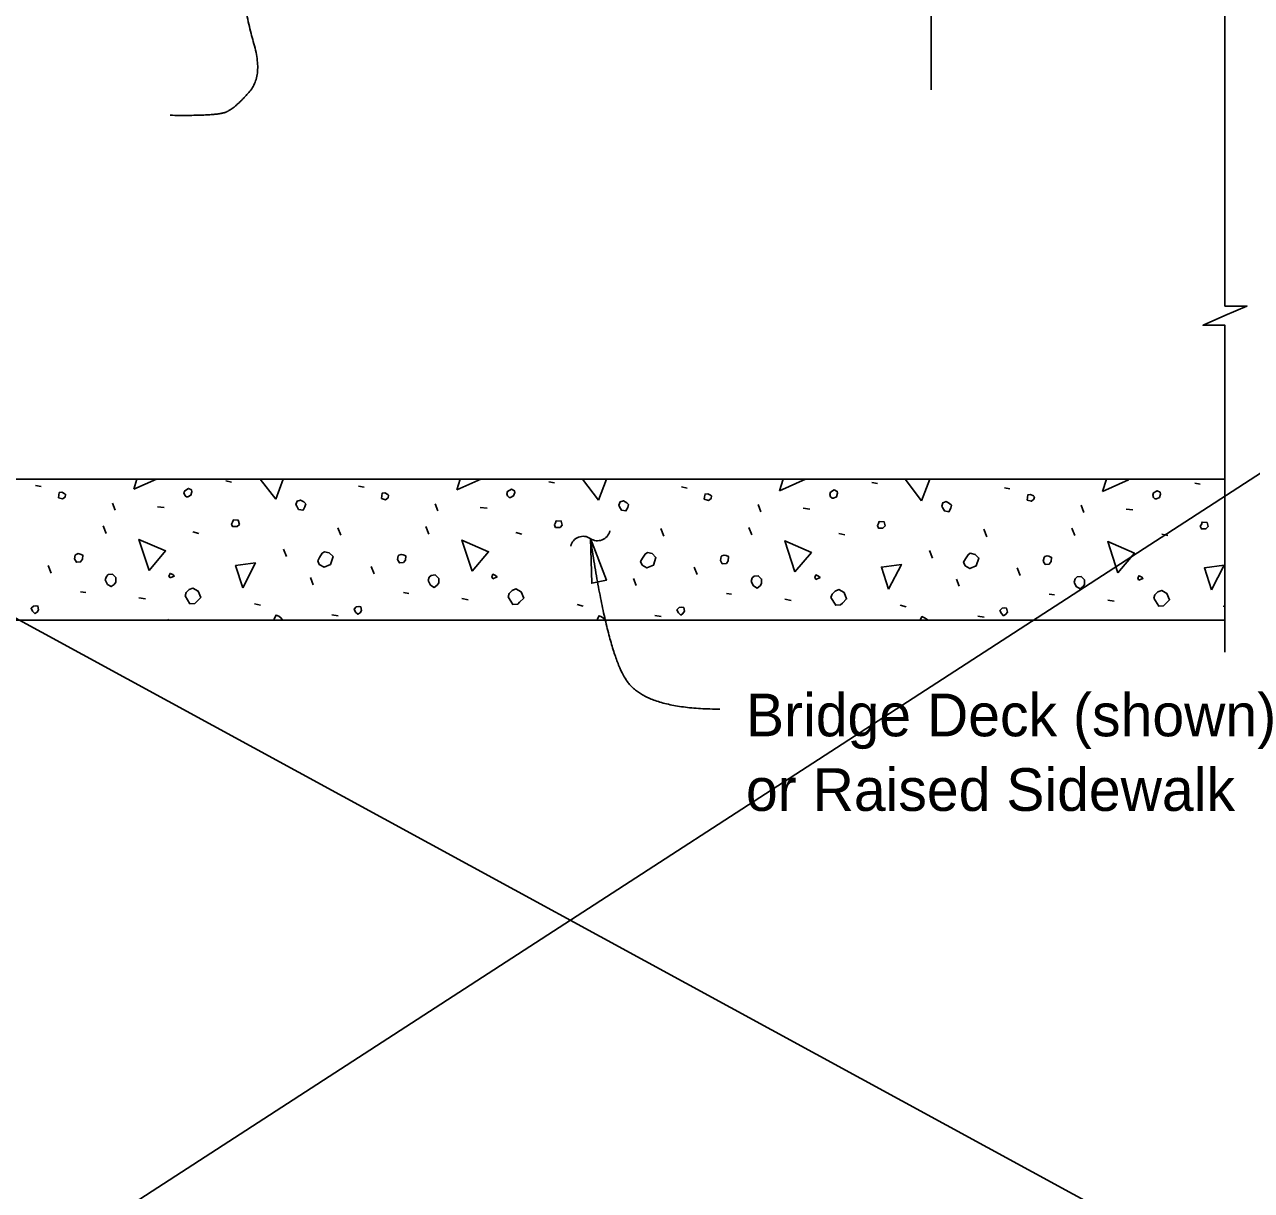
# Model space of a CAD drawing. Extents: x 110698 to 110915, y 110390 to 110472.
# Drawn here: x 110792.55 to 110798.34, y 110408.16 to 110413.66 of the extents above; entities that cross this region are included whole.
import ezdxf

# ---------------------------------------------------------------- set-up
doc = ezdxf.new("R2010")
doc.units = 0
for name, color, linetype in [('AdhocPoint_dp', 7, 'Continuous'), ('PlotBorder_dp', 7, 'Continuous'), ('SheetBorder_dp', 7, 'Continuous'), ('SheetLines_dp', 7, 'Continuous')]:
    doc.layers.add(name, color=color, linetype=linetype)

msp = doc.modelspace()

# ---------------------------------------------------------------- linework, layer by layer
at = {"layer": 'AdhocPoint_dp'}
msp.add_line((110796.8255, 110422.1361), (110796.8255, 110413.3542), dxfattribs=at)
at = {"layer": 'PlotBorder_dp'}
msp.add_lwpolyline([(110798.2126, 110413.7679), (110798.2126, 110412.334), (110798.3159, 110412.334), (110798.2126, 110412.289), (110798.1092, 110412.244), (110798.2126, 110412.244), (110798.2126, 110410.7015)], dxfattribs=at)
msp.add_lwpolyline([(110795.2186, 110411.2375), (110795.2247, 110411.0264), (110795.2939, 110411.0402)], close=True, dxfattribs=at)
for centre, start, end in [((110795.1839, 110411.188), 55.45253, 167.17975), ((110795.2516, 110411.2862), 235.45253, 347.17975)]:
    msp.add_arc(centre, 0.0596, start, end, dxfattribs=at)
for points in [[(110793.2353, 110413.2345), (110793.4581, 110413.2309), (110793.543, 110413.2699), (110793.6739, 110413.4186), (110793.589, 110413.716), (110793.5465, 110413.9813)], [(110795.8288, 110410.4321), (110795.4884, 110410.4321), (110795.2993, 110410.6877), (110795.2186, 110411.2376)]]:
    msp.add_open_spline(points, degree=2, dxfattribs=at)
at = {"layer": 'SheetBorder_dp'}
for p, q in [((110792.6001, 110411.4876), (110792.6266, 110411.4823)), ((110793.4981, 110411.5088), (110793.5246, 110411.5035)), ((110794.1239, 110411.4841), (110794.1504, 110411.4788)), ((110795.0219, 110411.5053), (110795.0485, 110411.5)), ((110795.6477, 110411.4805), (110795.6742, 110411.4752)), ((110796.5458, 110411.5018), (110796.5723, 110411.4965)), ((110797.1715, 110411.477), (110797.1981, 110411.4717)), ((110798.0696, 110411.4982), (110798.0961, 110411.4929)), ((110792.9749, 110411.3709), (110792.9625, 110411.4045)), ((110793.1746, 110411.3869), (110793.2064, 110411.3833)), ((110794.4987, 110411.3674), (110794.4863, 110411.401)), ((110794.6984, 110411.3833), (110794.7303, 110411.3798)), ((110796.0225, 110411.3639), (110796.0101, 110411.3975)), ((110796.2223, 110411.3798), (110796.2541, 110411.3762)), ((110797.5463, 110411.3603), (110797.5339, 110411.3939)), ((110797.7461, 110411.3762), (110797.7779, 110411.3727)), ((110792.9324, 110411.2613), (110792.9183, 110411.2967)), ((110794.4563, 110411.2578), (110794.4421, 110411.2932)), ((110795.9801, 110411.2543), (110795.9659, 110411.2896)), ((110793.3426, 110411.2684), (110793.3708, 110411.2613)), ((110794.0408, 110411.2525), (110794.0267, 110411.2879)), ((110794.8664, 110411.2649), (110794.8947, 110411.2578)), ((110795.5646, 110411.249), (110795.5505, 110411.2843)), ((110796.3902, 110411.2613), (110796.4185, 110411.2543)), ((110797.0885, 110411.2454), (110797.0743, 110411.2808)), ((110797.5039, 110411.2507), (110797.4897, 110411.2861)), ((110797.914, 110411.2578), (110797.9423, 110411.2507)), ((110793.7845, 110411.1517), (110793.7704, 110411.1871)), ((110796.8321, 110411.1447), (110796.818, 110411.18)), ((110792.6743, 110411.074), (110792.6602, 110411.1093)), ((110794.1982, 110411.0704), (110794.184, 110411.1058)), ((110795.722, 110411.0669), (110795.7078, 110411.1022)), ((110797.2458, 110411.0634), (110797.2316, 110411.0987)), ((110793.91, 110411.0192), (110793.8976, 110411.0527)), ((110795.4338, 110411.0156), (110795.4215, 110411.0492)), ((110796.9576, 110411.0121), (110796.9453, 110411.0457)), ((110792.8122, 110410.9856), (110792.837, 110410.982)), ((110793.088, 110410.9573), (110793.1181, 110410.952)), ((110794.336, 110410.982), (110794.3608, 110410.9785)), ((110794.6118, 110410.9537), (110794.6419, 110410.9484)), ((110795.8599, 110410.9785), (110795.8846, 110410.975)), ((110796.1356, 110410.9502), (110796.1657, 110410.9449)), ((110797.3837, 110410.975), (110797.4084, 110410.9714)), ((110797.6594, 110410.9467), (110797.6895, 110410.9414)), ((110793.6325, 110410.929), (110793.6608, 110410.9219)), ((110795.1563, 110410.9255), (110795.1846, 110410.9184)), ((110796.6801, 110410.9219), (110796.7084, 110410.9149)), ((110798.2039, 110410.9184), (110798.2125, 110410.9162)), ((110793.2261, 110410.8512), (110793.2241, 110410.8565)), ((110793.9984, 110410.8777), (110794.0285, 110410.8724)), ((110794.7486, 110410.8512), (110794.7479, 110410.853)), ((110795.5222, 110410.8742), (110795.5523, 110410.8689)), ((110797.046, 110410.8707), (110797.0761, 110410.8654))]:
    msp.add_line(p, q, dxfattribs=at)
for points in [[(110793.0633, 110411.4699), (110793.078, 110411.5179)], [(110793.17, 110411.5179), (110793.0633, 110411.4699)], [(110793.3107, 110411.4346), (110793.3178, 110411.4346), (110793.332, 110411.4417), (110793.3373, 110411.4576), (110793.3355, 110411.4664), (110793.3213, 110411.4735), (110793.3037, 110411.4629), (110793.3001, 110411.4523), (110793.3037, 110411.4417), (110793.3107, 110411.4346)], [(110793.7332, 110411.4222), (110793.6605, 110411.5179)], [(110793.769, 110411.5179), (110793.7332, 110411.4222)], [(110794.5871, 110411.4664), (110794.6029, 110411.5179)], [(110794.7017, 110411.5179), (110794.5871, 110411.4664)], [(110794.8346, 110411.431), (110794.8416, 110411.431), (110794.8558, 110411.4381), (110794.8611, 110411.454), (110794.8593, 110411.4629), (110794.8452, 110411.4699), (110794.8275, 110411.4593), (110794.8239, 110411.4487), (110794.8275, 110411.4381), (110794.8346, 110411.431)], [(110795.2571, 110411.4187), (110795.1816, 110411.5179)], [(110795.2941, 110411.5179), (110795.2571, 110411.4187)], [(110796.1109, 110411.4629), (110796.1278, 110411.5179)], [(110796.2323, 110411.5179), (110796.2329, 110411.5177), (110796.1109, 110411.4629)], [(110796.3584, 110411.4275), (110796.3654, 110411.4275), (110796.3796, 110411.4346), (110796.3849, 110411.4505), (110796.3831, 110411.4593), (110796.369, 110411.4664), (110796.3513, 110411.4558), (110796.3478, 110411.4452), (110796.3513, 110411.4346), (110796.3584, 110411.4275)], [(110796.7809, 110411.4151), (110796.7028, 110411.5179)], [(110796.8193, 110411.5179), (110796.7809, 110411.4151)], [(110797.6347, 110411.4593), (110797.6527, 110411.5179)], [(110797.7472, 110411.5179), (110797.7567, 110411.5141), (110797.6347, 110411.4593)], [(110792.7079, 110411.4293), (110792.7274, 110411.424), (110792.7398, 110411.4328), (110792.7415, 110411.4452), (110792.738, 110411.4487), (110792.7238, 110411.4558), (110792.7115, 110411.454), (110792.7097, 110411.4417), (110792.7079, 110411.4293)], [(110793.8322, 110411.3904), (110793.8411, 110411.3745), (110793.8623, 110411.3709), (110793.8711, 110411.3869), (110793.8747, 110411.401), (110793.8658, 110411.4098), (110793.8499, 110411.4187), (110793.834, 110411.4134), (110793.8287, 110411.3975), (110793.8322, 110411.3904)], [(110794.2317, 110411.4257), (110794.2512, 110411.4204), (110794.2636, 110411.4293), (110794.2653, 110411.4417), (110794.2618, 110411.4452), (110794.2477, 110411.4523), (110794.2353, 110411.4505), (110794.2335, 110411.4381), (110794.2317, 110411.4257)], [(110795.356, 110411.3869), (110795.3649, 110411.3709), (110795.3861, 110411.3674), (110795.3949, 110411.3833), (110795.3985, 110411.3975), (110795.3896, 110411.4063), (110795.3737, 110411.4151), (110795.3578, 110411.4098), (110795.3525, 110411.3939), (110795.356, 110411.3869)], [(110795.7556, 110411.4222), (110795.775, 110411.4169), (110795.7874, 110411.4257), (110795.7891, 110411.4381), (110795.7856, 110411.4417), (110795.7715, 110411.4487), (110795.7591, 110411.447), (110795.7573, 110411.4346), (110795.7556, 110411.4222)], [(110796.8799, 110411.3833), (110796.8887, 110411.3674), (110796.9099, 110411.3639), (110796.9188, 110411.3798), (110796.9223, 110411.3939), (110796.9134, 110411.4028), (110796.8975, 110411.4116), (110796.8816, 110411.4063), (110796.8763, 110411.3904), (110796.8799, 110411.3833)], [(110797.2794, 110411.4187), (110797.2988, 110411.4134), (110797.3112, 110411.4222), (110797.313, 110411.4346), (110797.3094, 110411.4381), (110797.2953, 110411.4452), (110797.2829, 110411.4434), (110797.2811, 110411.431), (110797.2794, 110411.4187)], [(110797.8822, 110411.424), (110797.8893, 110411.424), (110797.9034, 110411.431), (110797.9087, 110411.447), (110797.9069, 110411.4558), (110797.8928, 110411.4629), (110797.8751, 110411.4523), (110797.8716, 110411.4417), (110797.8751, 110411.431), (110797.8822, 110411.424)], [(110793.5299, 110411.2932), (110793.5512, 110411.2932), (110793.5618, 110411.3038), (110793.5565, 110411.3232), (110793.5335, 110411.325), (110793.5299, 110411.3144), (110793.5246, 110411.3055), (110793.5299, 110411.2932), (110793.5264, 110411.2967)], [(110795.0538, 110411.2896), (110795.075, 110411.2896), (110795.0856, 110411.3002), (110795.0803, 110411.3197), (110795.0573, 110411.3214), (110795.0538, 110411.3108), (110795.0485, 110411.302), (110795.0538, 110411.2896), (110795.0502, 110411.2932)], [(110796.5776, 110411.2861), (110796.5988, 110411.2861), (110796.6094, 110411.2967), (110796.6041, 110411.3161), (110796.5811, 110411.3179), (110796.5776, 110411.3073), (110796.5723, 110411.2985), (110796.5776, 110411.2861), (110796.574, 110411.2896)], [(110798.1014, 110411.2826), (110798.1226, 110411.2826), (110798.1332, 110411.2932), (110798.1279, 110411.3126), (110798.1049, 110411.3144), (110798.1014, 110411.3038), (110798.0961, 110411.2949), (110798.1014, 110411.2826), (110798.0979, 110411.2861)], [(110793.1357, 110411.0863), (110793.088, 110411.2331), (110793.2135, 110411.1783), (110793.1357, 110411.0863)], [(110793.9383, 110411.1146), (110793.9613, 110411.1022), (110793.9913, 110411.1146), (110794.0037, 110411.1517), (110793.986, 110411.1694), (110793.963, 110411.1747), (110793.9524, 110411.1676), (110793.9401, 110411.1482), (110793.9312, 110411.1323), (110793.9383, 110411.1146)], [(110794.6595, 110411.0828), (110794.6118, 110411.2295), (110794.7373, 110411.1747), (110794.6595, 110411.0828)], [(110796.1834, 110411.0793), (110796.1356, 110411.226), (110796.2611, 110411.1712), (110796.1834, 110411.0793)], [(110797.7072, 110411.0757), (110797.6594, 110411.2224), (110797.785, 110411.1676), (110797.7072, 110411.0757)], [(110792.7839, 110411.1411), (110792.7928, 110411.1252), (110792.8122, 110411.127), (110792.8211, 110411.1394), (110792.8228, 110411.1588), (110792.8105, 110411.1641), (110792.8016, 110411.1659), (110792.791, 110411.1623), (110792.7875, 110411.1588), (110792.7839, 110411.1411)], [(110793.5777, 110411.005), (110793.5441, 110411.1093), (110793.6378, 110411.1217), (110793.5777, 110411.005)], [(110794.3078, 110411.1376), (110794.3166, 110411.1217), (110794.336, 110411.1235), (110794.3449, 110411.1358), (110794.3467, 110411.1553), (110794.3343, 110411.1606), (110794.3254, 110411.1623), (110794.3148, 110411.1588), (110794.3113, 110411.1553), (110794.3078, 110411.1376)], [(110795.4621, 110411.1111), (110795.4851, 110411.0987), (110795.5151, 110411.1111), (110795.5275, 110411.1482), (110795.5098, 110411.1659), (110795.4869, 110411.1712), (110795.4763, 110411.1641), (110795.4639, 110411.1447), (110795.455, 110411.1288), (110795.4621, 110411.1111)], [(110795.8316, 110411.1341), (110795.8404, 110411.1182), (110795.8599, 110411.1199), (110795.8687, 110411.1323), (110795.8705, 110411.1517), (110795.8581, 110411.157), (110795.8493, 110411.1588), (110795.8386, 110411.1553), (110795.8351, 110411.1517), (110795.8316, 110411.1341)], [(110796.9859, 110411.1075), (110797.0089, 110411.0952), (110797.039, 110411.1075), (110797.0513, 110411.1447), (110797.0337, 110411.1623), (110797.0107, 110411.1676), (110797.0001, 110411.1606), (110796.9877, 110411.1411), (110796.9789, 110411.1252), (110796.9859, 110411.1075)], [(110797.3554, 110411.1305), (110797.3642, 110411.1146), (110797.3837, 110411.1164), (110797.3925, 110411.1288), (110797.3943, 110411.1482), (110797.3819, 110411.1535), (110797.3731, 110411.1553), (110797.3625, 110411.1517), (110797.3589, 110411.1482), (110797.3554, 110411.1305)], [(110792.9289, 110411.0421), (110792.9395, 110411.0209), (110792.9572, 110411.0103), (110792.9713, 110411.0209), (110792.9784, 110411.0315), (110792.9784, 110411.0527), (110792.9625, 110411.0687), (110792.943, 110411.0669), (110792.9342, 110411.058), (110792.9289, 110411.0421)], [(110793.2347, 110411.051), (110793.2542, 110411.0598), (110793.2471, 110411.0669), (110793.2347, 110411.0722), (110793.2294, 110411.0598), (110793.2347, 110411.051)], [(110794.4527, 110411.0386), (110794.4633, 110411.0174), (110794.481, 110411.0068), (110794.4951, 110411.0174), (110794.5022, 110411.028), (110794.5022, 110411.0492), (110794.4863, 110411.0651), (110794.4669, 110411.0634), (110794.458, 110411.0545), (110794.4527, 110411.0386)], [(110794.7585, 110411.0474), (110794.778, 110411.0563), (110794.7709, 110411.0634), (110794.7585, 110411.0687), (110794.7532, 110411.0563), (110794.7585, 110411.0474)], [(110795.9765, 110411.0351), (110795.9871, 110411.0139), (110796.0048, 110411.0032), (110796.019, 110411.0139), (110796.026, 110411.0245), (110796.026, 110411.0457), (110796.0101, 110411.0616), (110795.9907, 110411.0598), (110795.9818, 110411.051), (110795.9765, 110411.0351)], [(110796.2824, 110411.0439), (110796.3018, 110411.0527), (110796.2947, 110411.0598), (110796.2824, 110411.0651), (110796.2771, 110411.0527), (110796.2824, 110411.0439)], [(110796.6253, 110410.9979), (110796.5917, 110411.1022), (110796.6854, 110411.1146), (110796.6253, 110410.9979)], [(110797.5003, 110411.0315), (110797.511, 110411.0103), (110797.5286, 110410.9997), (110797.5428, 110411.0103), (110797.5498, 110411.0209), (110797.5498, 110411.0421), (110797.5339, 110411.058), (110797.5145, 110411.0563), (110797.5057, 110411.0474), (110797.5003, 110411.0315)], [(110797.8062, 110411.0404), (110797.8256, 110411.0492), (110797.8185, 110411.0563), (110797.8062, 110411.0616), (110797.8009, 110411.0492), (110797.8062, 110411.0404)], [(110798.1491, 110410.9944), (110798.1155, 110411.0987), (110798.2092, 110411.1111), (110798.1491, 110410.9944)], [(110793.3054, 110410.9661), (110793.3284, 110410.929), (110793.3514, 110410.9308), (110793.3602, 110410.9396), (110793.3797, 110410.9591), (110793.3673, 110410.9891), (110793.3426, 110411.0032), (110793.3249, 110410.9962), (110793.3107, 110410.982), (110793.3054, 110410.9661)], [(110794.8293, 110410.9626), (110794.8522, 110410.9255), (110794.8752, 110410.9272), (110794.8841, 110410.9361), (110794.9035, 110410.9555), (110794.8911, 110410.9856), (110794.8664, 110410.9997), (110794.8487, 110410.9926), (110794.8346, 110410.9785), (110794.8293, 110410.9626)], [(110796.3531, 110410.9591), (110796.376, 110410.9219), (110796.399, 110410.9237), (110796.4079, 110410.9325), (110796.4273, 110410.952), (110796.4149, 110410.982), (110796.3902, 110410.9962), (110796.3725, 110410.9891), (110796.3584, 110410.975), (110796.3531, 110410.9591)], [(110797.8769, 110410.9555), (110797.8999, 110410.9184), (110797.9228, 110410.9202), (110797.9317, 110410.929), (110797.9511, 110410.9484), (110797.9388, 110410.9785), (110797.914, 110410.9926), (110797.8963, 110410.9856), (110797.8822, 110410.9714), (110797.8769, 110410.9555)], [(110792.586, 110410.8936), (110792.5966, 110410.883), (110792.6072, 110410.8901), (110792.6142, 110410.9007), (110792.6107, 110410.9184), (110792.6019, 110410.9202), (110792.5895, 110410.9184), (110792.5789, 110410.9078), (110792.586, 110410.8936)], [(110794.1098, 110410.8901), (110794.1204, 110410.8795), (110794.131, 110410.8866), (110794.1381, 110410.8972), (110794.1345, 110410.9149), (110794.1257, 110410.9166), (110794.1133, 110410.9149), (110794.1027, 110410.9043), (110794.1098, 110410.8901)], [(110795.6336, 110410.8866), (110795.6442, 110410.876), (110795.6548, 110410.883), (110795.6619, 110410.8936), (110795.6583, 110410.9113), (110795.6495, 110410.9131), (110795.6371, 110410.9113), (110795.6265, 110410.9007), (110795.6336, 110410.8866)], [(110797.1574, 110410.883), (110797.168, 110410.8724), (110797.1786, 110410.8795), (110797.1857, 110410.8901), (110797.1821, 110410.9078), (110797.1733, 110410.9096), (110797.1609, 110410.9078), (110797.1503, 110410.8972), (110797.1574, 110410.883)], [(110793.7621, 110410.8512), (110793.7633, 110410.8548), (110793.758, 110410.8636), (110793.7474, 110410.8707), (110793.735, 110410.876), (110793.7279, 110410.8618), (110793.7244, 110410.8512)], [(110795.2871, 110410.8512), (110795.2818, 110410.8601), (110795.2712, 110410.8671), (110795.2588, 110410.8724), (110795.2517, 110410.8583), (110795.2494, 110410.8512)], [(110796.8088, 110410.8512), (110796.8056, 110410.8565), (110796.795, 110410.8636), (110796.7826, 110410.8689), (110796.7756, 110410.8548), (110796.7744, 110410.8512)]]:
    msp.add_lwpolyline(points, dxfattribs=at)
at = {"layer": 'SheetLines_dp'}
for p, q in [((110767.7236, 110424.3517), (110816.3335, 110397.8895)), ((110815.4706, 110422.6259), (110773.7639, 110395.5884)), ((110775.4386, 110411.5179), (110798.2125, 110411.5179)), ((110775.4386, 110410.8512), (110798.2125, 110410.8512))]:
    msp.add_line(p, q, dxfattribs=at)

# ---------------------------------------------------------------- texts
at = {"layer": 'PlotBorder_dp'}
for s, p in [('Bridge Deck (shown)', (110795.9521, 110410.3038)), ('or Raised Sidewalk', (110795.9521, 110409.9518))]:
    msp.add_text(s, height=0.2016, dxfattribs=at).set_placement(p)

doc.saveas('drawing.dxf')
